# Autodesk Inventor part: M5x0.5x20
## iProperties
IsCustomPart: 0
Company: 한국ATC센터
Created: 2009-02
Part Number: M5x0.5x20
Material: Steel, Mild
Description: 6각머리 태핑 나사
Document SubType Name: Modeling
Standard: KS B 1003
Designer: KYOUNG IL JANG
Standards Organization: KS
Language: ko-KR
Size Designation: M 5 x 20
Categories: <MemberInstance><Categories><Category DisplayName="조임쇠" InternalName="e4da775c-781d-43d5-af7c-5136215cf5a6" Mnemonic="FSTN"><Category DisplayName="볼트" InternalN
Density: 7.86 g/cm^3
Mass: 4.9629 g
Surface Area: 5.88238 cm^2
Volume: 0.631412 cm^3
Author: KYOUNG IL JANG
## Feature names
1. Fillet2
